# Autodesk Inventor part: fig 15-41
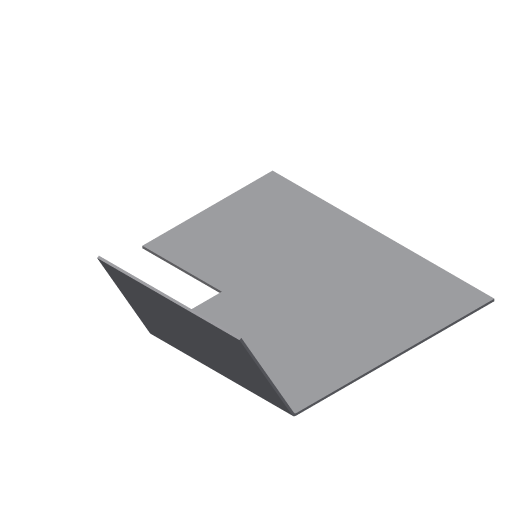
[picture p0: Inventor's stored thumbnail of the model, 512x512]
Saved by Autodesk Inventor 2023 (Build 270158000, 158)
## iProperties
Created: 2005-03
Part Number: fig 15-41
Document SubType Name: Sheet Metal
Designer: CADCIM
Manufacturer: Standard
Standards Organization: Custom
Density: 1 g/cm^3
Sheet Metal Rule: Default
Material: Generic
Appearance: Default
Author: CADCIM
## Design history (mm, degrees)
node "Face1"
  sketch "Sketch1"
    geometry: L1 (31.393, 35.714)-(-19.875, 35.714); L2 (-19.875, 35.714)-(-19.875, 5.625); L3 (-19.875, 5.625)-(-1.5, 5.625); L4 (-1.5, 5.625)-(-1.5, -10.705); L5 (-1.5, -10.705)-(31.393, -10.705); L6 (31.393, -10.705)-(31.393, 35.714)
    constraints: 12 end point, 4 parallel, 1 horizontal, 1 perpendicular
sketch "Sketch3"
  geometry: L1 (18.375, -30.089)-(18.375, 0); L2 (18.375, -46.42)-(18.375, -30.089) reference; L3 (18.375, -30.089)-(0, -30.089) reference; L4 (0, 0)-(51.268, 0) reference
  constraints: 3 point on line, 2 end point, 1 vertical
node "Flange1"
body "Solid1"
face "Plate1" dims "d11" = 0.5 (= Thickness)
sketch "Sketch4"
  geometry: L1 through (-16.446, 0) direction (1, 0); L2 through (0, 12.5) direction (-6.75e-17, 1); L3 (0, 25)-(-32.893, 25); L4 (-32.893, 25)-(-32.893, 0)
  constraints: 6 end point, 1 horizontal, 1 perpendicular, 1 vertical
face "Plate2" dims "d1" = 0.5 (= BendReliefWidth), "d2" = 0.25 (= BendReliefDepth), "d3" = 1 (= MinimumRemnant), "d4" = 0.5 (= BendRadius), "d5" = 25, "d6" = 60 deg, "d7" = 0.5 (= BendRadius), "d8" = 2 (= CornerReliefSize), "d9" = 0.5 (= GapSize), "d10" = 0.5 (= JacobiRadiusSize), "d11" = 0.5 (= Thickness), "SeamGap" = 0.01
bend "Bend1" dims "d1" = 0.5 (= BendReliefWidth), "d2" = 0.25 (= BendReliefDepth), "d3" = 1 (= MinimumRemnant), "d4" = 0.5 (= BendRadius), "d5" = 25, "d6" = 60 deg, "d7" = 0.5 (= BendRadius), "d11" = 0.5 (= Thickness), "SeamGap" = 0.01
feature "Corner1" dims "d5" = 25, "d6" = 60 deg, "d8" = 2 (= CornerReliefSize), "d9" = 0.5 (= GapSize), "d10" = 0.5 (= JacobiRadiusSize)
other parameters: "Thickness" = 0.5, "BendRadius" = 0.5 (= Thickness), "BendReliefWidth" = 0.5 (= Thickness), "BendReliefDepth" = 0.25 (= 0.5 x Thickness), "CornerReliefSize" = 2 (= 4 x Thickness), "MinimumRemnant" = 1 (= 2 x Thickness), "TransitionRadius" = 0.5 (= BendRadius), "d0" = 0.5 (= BendRadius), "JacobiRadiusSize" = 0.5 (= Thickness), "GapSize" = 0.5 (= Thickness)
